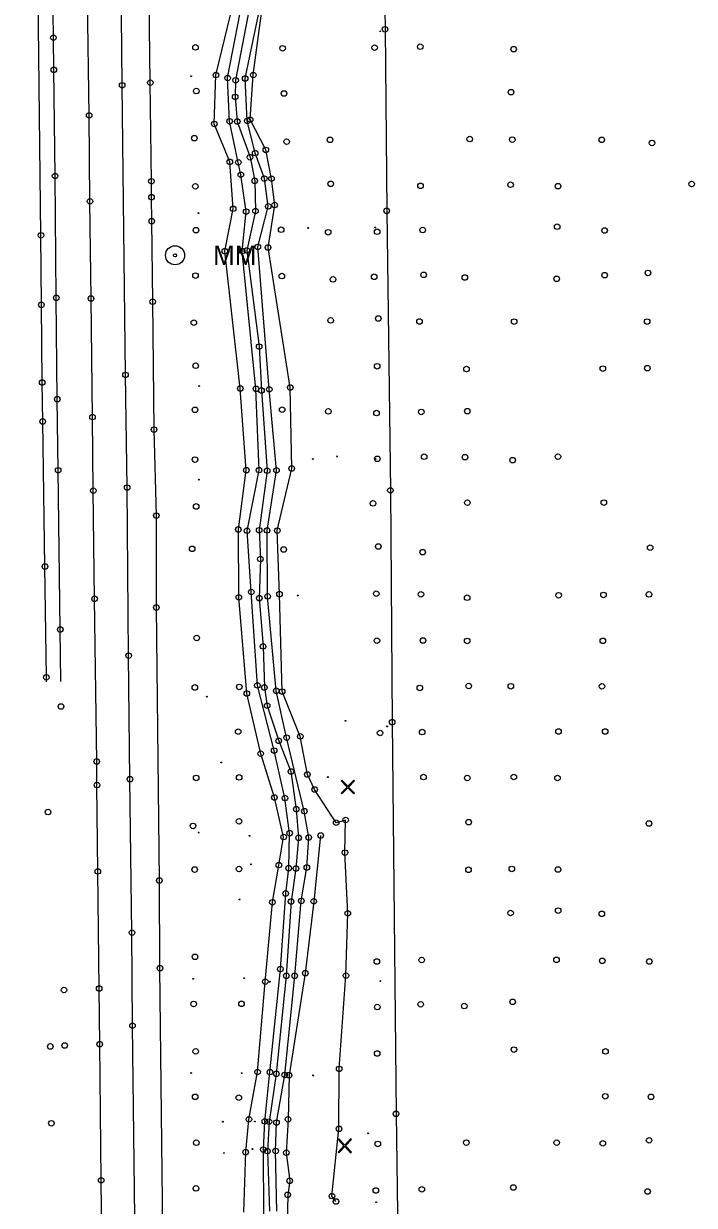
# Model space of a CAD drawing. Extents: x 20503438 to 20508873, y 7964251 to 7984667.
# Drawn here: x 20505454.4 to 20505695.9, y 7981861 to 7982286.2 of the extents above; entities that cross this region are included whole.
import ezdxf

# ---------------------------------------------------------------- set-up
doc = ezdxf.new("R2010")
doc.units = 0
for name, color, linetype in [('SurBreakLine', 7, 'Continuous'), ('SurControl', 7, 'Continuous'), ('SurDrainageArrowUp', 7, 'Continuous'), ('SurEdgeRoadPaved', 7, 'Continuous'), ('SurEdgeShoulderPaved', 7, 'Continuous'), ('SurFenceWire', 7, 'Continuous'), ('SurPointsNonDTM', 7, 'Continuous'), ('SurRoadPoints', 7, 'Continuous'), ('SurSurveyPoints', 7, 'Continuous')]:
    doc.layers.add(name, color=color, linetype=linetype)

msp = doc.modelspace()

# ---------------------------------------------------------------- linework, layer by layer
at = {"layer": 'SurBreakLine'}
for points in [[(20505533.66, 7981858.56), (20505534.37, 7981880.13), (20505535.54, 7981891.92), (20505538.65, 7981908.97), (20505541.43, 7981941.46), (20505544, 7981970.04), (20505546.31, 7981983.42), (20505548.03, 7981993.51), (20505544.72, 7982007.73), (20505539.77, 7982023.51), (20505534.8, 7982045.17), (20505531.92, 7982079.77), (20505531.73, 7982104.19), (20505534.58, 7982125.53), (20505532.44, 7982154.9), (20505526.86, 7982204.31), (20505529.86, 7982219.58), (20505528.68, 7982236.47), (20505523.06, 7982250.12), (20505523.65, 7982267.68), (20505531.03, 7982298.4)], [(20505540.86, 7981857.16), (20505540.73, 7981881.04), (20505541.27, 7981891.19), (20505543.11, 7981908.93), (20505546.87, 7981946.01), (20505548.79, 7981973.2), (20505549.87, 7981982.29), (20505550.18, 7981994.89), (20505548.49, 7982007.54), (20505544.64, 7982024.62), (20505538.6, 7982048.07), (20505536.39, 7982081.69), (20505534.88, 7982103.73), (20505539.2, 7982125.55), (20505538.07, 7982154.79), (20505533.09, 7982204.37), (20505534.53, 7982218.56), (20505532.62, 7982231.85), (20505531.72, 7982236.28), (20505528.58, 7982251.08), (20505527.86, 7982266.64), (20505534.23, 7982299.42)], [(20505482.66, 7981838.18), (20505482.35, 7981869.99), (20505481.84, 7981919), (20505481.63, 7981939.03), (20505481.16, 7981981.15), (20505480.82, 7982012.22), (20505480.73, 7982020.7), (20505479.97, 7982079.23), (20505479.51, 7982118.14), (20505479.21, 7982144.63), (20505478.7, 7982187.28), (20505478.32, 7982222.25), (20505478.02, 7982253.21), (20505477.45, 7982295.16)], [(20505545.64, 7981858.92), (20505545.16, 7981880.55), (20505545.45, 7981890.75), (20505548.44, 7981907.9), (20505552.02, 7981943.58), (20505554.39, 7981970.53), (20505556.38, 7981982.54), (20505557.08, 7981993.33), (20505555.48, 7982002.81), (20505549.12, 7982029.29), (20505545.37, 7982046.14), (20505542.28, 7982080.11), (20505542.08, 7982103.84), (20505545.47, 7982125.46), (20505542.85, 7982154.62), (20505538.74, 7982205.85), (20505542.5, 7982220.43), (20505541.11, 7982230.43), (20505537.79, 7982239.62), (20505534.95, 7982251.19), (20505534.2, 7982266.46), (20505540.46, 7982296.4)], [(20505566.86, 7981862.36), (20505565.41, 7981864.32), (20505567.96, 7981888.53), (20505568.01, 7981910.06), (20505570.48, 7981943.64), (20505571.16, 7981966.05), (20505570.1, 7981987.9), (20505570.34, 7981999.63), (20505566.96, 7981998.68), (20505559.2, 7982010.61), (20505556.59, 7982016.02), (20505554.01, 7982029.73), (20505547.49, 7982045.85), (20505546.56, 7982080.9), (20505545.76, 7982103.77), (20505550.95, 7982126.11), (20505550.41, 7982155.27), (20505542.43, 7982205.63), (20505544.81, 7982220.91), (20505543.66, 7982230.41), (20505541.61, 7982240.76), (20505535.97, 7982251.65), (20505537.1, 7982267.72), (20505540.88, 7982296.21)], [(20505561.36, 7981994.08), (20505558.88, 7981970.37), (20505555.83, 7981944.51), (20505549.98, 7981907.82), (20505549.62, 7981891.93), (20505549, 7981879.91), (20505550.23, 7981869.81), (20505549.51, 7981864.77), (20505549.3, 7981853.83), (20505549.91, 7981848.75), (20505553.2, 7981847.61)]]:
    msp.add_lwpolyline(points, dxfattribs=at)
at = {"layer": 'SurControl'}
for points in [[(20505573.56, 7982013.74), (20505573.3, 7982013.99), (20505571.16, 7982011.77), (20505569.02, 7982013.99), (20505568.76, 7982013.74), (20505570.91, 7982011.51), (20505568.76, 7982009.28), (20505569.02, 7982009.03), (20505571.16, 7982011.25), (20505573.3, 7982009.03), (20505573.56, 7982009.28), (20505571.41, 7982011.51)], [(20505572.41, 7981884.62), (20505572.15, 7981884.87), (20505570.01, 7981882.65), (20505567.87, 7981884.87), (20505567.61, 7981884.62), (20505569.76, 7981882.39), (20505567.61, 7981880.16), (20505567.87, 7981879.91), (20505570.01, 7981882.13), (20505572.15, 7981879.91), (20505572.41, 7981880.16), (20505570.26, 7981882.39)]]:
    msp.add_lwpolyline(points, close=True, dxfattribs=at)
for centre in [(20505582.84, 7982283.42), (20505514.72, 7982267.28), (20505517.35, 7982218.01), (20505556.9, 7982212.68), (20505581.02, 7982212.82), (20505517.64, 7982155.82), (20505558.52, 7982129.53), (20505567.24, 7982130.47), (20505581.09, 7982129.57), (20505517.46, 7982122.09), (20505553.1, 7982080.44), (20505520.36, 7982044.02), (20505570.32, 7982035.3), (20505585.33, 7982033.33), (20505525.55, 7982020.33), (20505563.96, 7982015.1), (20505517.45, 7981995.11), (20505535.78, 7981993.92), (20505536.18, 7981983.69), (20505532.19, 7981971.05), (20505515.45, 7981942.49), (20505533.81, 7981942.73), (20505543.03, 7981941.44), (20505582.85, 7981941.69), (20505514.74, 7981908.6), (20505532.92, 7981908.53), (20505558.7, 7981907.75), (20505526.13, 7981891.07), (20505537.66, 7981891.18), (20505578.49, 7981886.9), (20505536.86, 7981881.23), (20505526.56, 7981879.81), (20505581.34, 7981862.1)]:
    msp.add_circle(centre, 0.15, dxfattribs=at)
at = {"layer": 'SurDrainageArrowUp'}
msp.add_lwpolyline([(20505536.79, 7982297.77), (20505530.73, 7982265.81), (20505530.59, 7982259.82), (20505531.33, 7982250.97), (20505535.93, 7982238.11), (20505537.61, 7982229.63), (20505537.92, 7982218.79), (20505534.78, 7982204.62), (20505539.23, 7982169.99), (20505540.07, 7982154.17), (20505542.1, 7982125.32), (20505539.21, 7982103.89), (20505539.68, 7982093.54), (20505539.25, 7982079.46), (20505540.64, 7982062.1), (20505541.1, 7982047.32), (20505542.09, 7982040.78), (20505546.28, 7982028.14), (20505550.66, 7982017.09), (20505552.57, 7982003.52), (20505553.43, 7981993.22), (20505552.45, 7981982.2), (20505550.72, 7981970.32), (20505548.99, 7981943.58), (20505545.4, 7981908.32), (20505542.77, 7981891.09), (20505542.19, 7981880.5), (20505542.98, 7981858.88)], dxfattribs=at)
at = {"layer": 'SurEdgeRoadPaved'}
for points in [[(20505495.04, 7981807.4), (20505493.61, 7981925.64), (20505493.44, 7981959.11), (20505492.72, 7982014.35), (20505492.22, 7982058.8), (20505491.71, 7982119.25), (20505491.09, 7982159.8), (20505489.91, 7982264.01), (20505489.66, 7982289.18), (20505487.48, 7982484.19), (20505486.86, 7982538.99), (20505486.36, 7982623.82), (20505485.4, 7982711.25), (20505484.93, 7982775.73), (20505484.31, 7982835.82)], [(20505467.81, 7982049.46), (20505467.61, 7982068.18), (20505466.87, 7982125.48), (20505466.54, 7982151.08), (20505466.17, 7982187.53), (20505465.76, 7982231.38), (20505465.31, 7982269.59), (20505465.16, 7982281.14), (20505464.61, 7982327.96), (20505463.62, 7982409.11), (20505462.56, 7982525.93), (20505461.58, 7982636.16), (20505461.28, 7982673.07), (20505460.57, 7982745.92), (20505460.02, 7982819.87)]]:
    msp.add_lwpolyline(points, dxfattribs=at)
at = {"layer": 'SurEdgeShoulderPaved'}
for points in [[(20505504.9, 7981820.5), (20505503.51, 7981946.34), (20505503.3, 7981977.89), (20505502.21, 7982076.11), (20505502.21, 7982109.18), (20505501.39, 7982140.13), (20505500.91, 7982186.13), (20505500.55, 7982215.12), (20505500.48, 7982223.74), (20505500.44, 7982229.48), (20505500.04, 7982264.96), (20505498.78, 7982363.61), (20505498.7, 7982393.65), (20505498.03, 7982438.84), (20505497.19, 7982508.63), (20505496.45, 7982610.94), (20505496.22, 7982654.28), (20505495.42, 7982717.71), (20505495.4, 7982754.06), (20505495.09, 7982782.36), (20505493.62, 7982896.29)], [(20505462.63, 7982049.4), (20505462.61, 7982051), (20505462.11, 7982090.85), (20505461.3, 7982143.05), (20505461.11, 7982157.07), (20505460.83, 7982185.02), (20505460.68, 7982210.05), (20505459.25, 7982328.4), (20505458.74, 7982376.86), (20505458.32, 7982412.29), (20505458.06, 7982438.23), (20505457.12, 7982523.38), (20505456.64, 7982592.43), (20505456.16, 7982626.15), (20505455.68, 7982697.33), (20505455.16, 7982733.14), (20505454.87, 7982799.91), (20505454.43, 7982834.05)]]:
    msp.add_lwpolyline(points, dxfattribs=at)
at = {"layer": 'SurFenceWire'}
msp.add_lwpolyline([(20505583.74, 7982820.12), (20505580.19, 7982701.02), (20505581.22, 7982574.25), (20505581.59, 7982491.04), (20505582.46, 7982428.28), (20505582.73, 7982421.79), (20505583.15, 7982367.8), (20505584.54, 7982284.18), (20505585.13, 7982218.82), (20505586.48, 7982118.26), (20505587.09, 7982034.84), (20505588.49, 7981893.92), (20505589.47, 7981822.49), (20505590.29, 7981766.07)], dxfattribs=at)
at = {"layer": 'SurPointsNonDTM'}
for centre in [(20505584.54, 7982284.18), (20505585.13, 7982218.82), (20505586.48, 7982118.26), (20505587.09, 7982034.84), (20505588.49, 7981893.92)]:
    msp.add_circle(centre, 1, dxfattribs=at)
at = {"layer": 'SurRoadPoints'}
for radius in [3.43, 0.571]:
    msp.add_circle((20505508.95, 7982202.84), radius, dxfattribs=at)
at = {"layer": 'SurSurveyPoints'}
for centre in [(20505465.16, 7982281.14), (20505516.29, 7982277.65), (20505547.65, 7982277.34), (20505580.77, 7982277.54), (20505597.21, 7982277.89), (20505630.85, 7982277.03), (20505465.31, 7982269.59), (20505523.65, 7982267.68), (20505527.86, 7982266.64), (20505537.1, 7982267.72), (20505489.91, 7982264.01), (20505500.04, 7982264.96), (20505530.73, 7982265.81), (20505534.2, 7982266.46), (20505516.6, 7982261.93), (20505530.59, 7982259.82), (20505548.16, 7982261.04), (20505629.88, 7982261.54), (20505478.02, 7982253.21), (20505523.06, 7982250.12), (20505528.58, 7982251.08), (20505531.33, 7982250.97), (20505534.95, 7982251.19), (20505535.97, 7982251.65), (20505515.88, 7982244.99), (20505549.12, 7982243.73), (20505564.75, 7982244.37), (20505615.04, 7982244.66), (20505630.34, 7982244.46), (20505662.56, 7982244.37), (20505680.64, 7982243.27), (20505535.93, 7982238.11), (20505537.79, 7982239.62), (20505541.61, 7982240.76), (20505528.68, 7982236.47), (20505531.72, 7982236.28), (20505465.76, 7982231.38), (20505500.44, 7982229.48), (20505532.62, 7982231.85), (20505537.61, 7982229.63), (20505541.11, 7982230.43), (20505543.66, 7982230.41), (20505565, 7982228.57), (20505694.9, 7982228.5), (20505516.27, 7982227.65), (20505597.29, 7982227.83), (20505629.73, 7982228.22), (20505646.83, 7982227.71), (20505478.32, 7982222.25), (20505500.48, 7982223.74), (20505542.5, 7982220.43), (20505544.81, 7982220.91), (20505529.86, 7982219.58), (20505534.53, 7982218.56), (20505537.92, 7982218.79), (20505500.55, 7982215.12), (20505516.47, 7982211.87), (20505547.16, 7982212.03), (20505581.71, 7982211.31), (20505598.09, 7982211.92), (20505646.49, 7982213.12), (20505663.57, 7982211.75), (20505460.68, 7982210.05), (20505564.08, 7982211.13), (20505526.86, 7982204.31), (20505533.09, 7982204.37), (20505534.78, 7982204.62), (20505538.74, 7982205.85), (20505542.43, 7982205.63), (20505516.3, 7982195.54), (20505547.38, 7982195.37), (20505580.63, 7982195.11), (20505598.42, 7982195.82), (20505613.26, 7982194.84), (20505646.35, 7982194.38), (20505663.59, 7982195.68), (20505679.18, 7982196.5), (20505565.81, 7982194.17), (20505466.17, 7982187.53), (20505478.7, 7982187.28), (20505500.91, 7982186.13), (20505460.83, 7982185.02), (20505515.7, 7982178.59), (20505564.96, 7982179.41), (20505582.13, 7982180.08), (20505596.95, 7982179.01), (20505631.01, 7982178.97), (20505678.91, 7982178.99), (20505539.23, 7982169.99), (20505516.39, 7982163.09), (20505581.69, 7982162.92), (20505613.86, 7982161.9), (20505662.93, 7982162.06), (20505678.98, 7982162.21), (20505461.11, 7982157.07), (20505491.09, 7982159.8), (20505532.44, 7982154.9), (20505538.07, 7982154.79), (20505540.07, 7982154.17), (20505542.85, 7982154.62), (20505550.41, 7982155.27), (20505466.54, 7982151.08), (20505479.21, 7982144.63), (20505516.11, 7982147.23), (20505547.52, 7982147.29), (20505564.14, 7982146.67), (20505581.47, 7982146.06), (20505597.57, 7982146.47), (20505614.17, 7982146.76), (20505461.3, 7982143.05), (20505501.39, 7982140.13), (20505516.12, 7982129.33), (20505581.75, 7982129.59), (20505598.62, 7982130.36), (20505613.35, 7982130.19), (20505630.47, 7982129.13), (20505646.79, 7982130.38), (20505466.87, 7982125.48), (20505534.58, 7982125.53), (20505539.2, 7982125.55), (20505542.1, 7982125.32), (20505545.47, 7982125.46), (20505550.95, 7982126.11), (20505479.51, 7982118.14), (20505491.71, 7982119.25), (20505580.18, 7982113.57), (20505614.17, 7982113.83), (20505663.31, 7982113.85), (20505516.56, 7982112.47), (20505502.21, 7982109.18), (20505531.73, 7982104.19), (20505534.88, 7982103.73), (20505539.21, 7982103.89), (20505542.08, 7982103.84), (20505545.76, 7982103.77), (20505515.1, 7982097.21), (20505548.06, 7982096.98), (20505582.11, 7982098.06), (20505680, 7982097.63), (20505539.68, 7982093.54), (20505598.09, 7982096.03), (20505462.11, 7982090.85), (20505531.92, 7982079.77), (20505536.39, 7982081.69), (20505539.25, 7982079.46), (20505542.28, 7982080.11), (20505546.56, 7982080.9), (20505581.37, 7982081.09), (20505597.45, 7982080.85), (20505614.12, 7982079.62), (20505647.04, 7982080.51), (20505663.18, 7982080.62), (20505679.54, 7982080.82), (20505479.97, 7982079.23), (20505502.21, 7982076.11), (20505467.61, 7982068.18), (20505516.75, 7982065.13), (20505581.61, 7982064.18), (20505598.21, 7982064.22), (20505614.09, 7982064.07), (20505662.95, 7982064.11), (20505492.22, 7982058.8), (20505540.64, 7982062.1), (20505462.61, 7982051), (20505516.08, 7982047.34), (20505532.05, 7982047.53), (20505538.6, 7982048.07), (20505541.1, 7982047.32), (20505545.37, 7982046.14), (20505547.49, 7982045.85), (20505597.08, 7982047.17), (20505614.67, 7982047.87), (20505629.82, 7982047.77), (20505662.62, 7982047.75), (20505534.8, 7982045.17), (20505467.91, 7982040.47), (20505542.09, 7982040.78), (20505531.65, 7982031.42), (20505549.12, 7982029.29), (20505554.01, 7982029.73), (20505582.76, 7982030.95), (20505597.92, 7982031.27), (20505647, 7982031.5), (20505663.77, 7982031.48), (20505544.64, 7982024.62), (20505546.28, 7982028.14), (20505480.73, 7982020.7), (20505539.77, 7982023.51), (20505550.66, 7982017.09), (20505556.59, 7982016.02), (20505480.82, 7982012.22), (20505492.72, 7982014.35), (20505516.54, 7982014.79), (20505532.01, 7982014.96), (20505598.38, 7982015.1), (20505614.15, 7982014.75), (20505630.92, 7982015.12), (20505646.63, 7982014.75), (20505544.72, 7982007.73), (20505548.49, 7982007.54), (20505559.2, 7982010.61), (20505552.57, 7982003.52), (20505463.22, 7982002.49), (20505531.99, 7981999.17), (20505555.48, 7982002.81), (20505566.96, 7981998.68), (20505570.34, 7981999.63), (20505614.62, 7981998.86), (20505515.42, 7981997.51), (20505550.18, 7981994.89), (20505679.55, 7981998.4), (20505548.03, 7981993.51), (20505553.43, 7981993.22), (20505557.08, 7981993.33), (20505561.36, 7981994.08), (20505570.1, 7981987.9), (20505516, 7981981.81), (20505531.98, 7981982.02), (20505546.31, 7981983.42), (20505549.87, 7981982.29), (20505552.45, 7981982.2), (20505556.38, 7981982.54), (20505614.58, 7981981.73), (20505630.17, 7981982.04), (20505646.82, 7981981.84), (20505481.16, 7981981.15), (20505503.3, 7981977.89), (20505548.79, 7981973.2), (20505544, 7981970.04), (20505550.72, 7981970.32), (20505554.39, 7981970.53), (20505558.88, 7981970.37), (20505571.16, 7981966.05), (20505629.73, 7981966.18), (20505646.87, 7981967.03), (20505662.59, 7981965.89), (20505493.44, 7981959.11), (20505516.14, 7981950.4), (20505581.6, 7981948.74), (20505597.72, 7981949.27), (20505646.26, 7981949.31), (20505662.73, 7981948.96), (20505679.69, 7981948.73), (20505503.51, 7981946.34), (20505546.87, 7981946.01), (20505548.99, 7981943.58), (20505552.02, 7981943.58), (20505555.83, 7981944.51), (20505570.48, 7981943.64), (20505541.43, 7981941.46), (20505468.96, 7981938.47), (20505481.63, 7981939.03), (20505515.64, 7981933.45), (20505532.86, 7981933.5), (20505581.76, 7981932.33), (20505597.37, 7981933.31), (20505613.05, 7981932.69), (20505630.49, 7981934.22), (20505493.61, 7981925.64), (20505464.05, 7981918.16), (20505469.2, 7981918.48), (20505481.84, 7981919), (20505516.37, 7981916.41), (20505581.69, 7981915.62), (20505630.93, 7981917.03), (20505663.92, 7981916.37), (20505568.01, 7981910.06), (20505538.65, 7981908.97), (20505543.11, 7981908.93), (20505545.4, 7981908.32), (20505548.44, 7981907.9), (20505549.98, 7981907.82), (20505516.18, 7981900.04), (20505531.92, 7981899.74), (20505663.81, 7981900.24), (20505680.29, 7981900.03), (20505464.43, 7981890.53), (20505535.54, 7981891.92), (20505541.27, 7981891.19), (20505542.77, 7981891.09), (20505545.45, 7981890.75), (20505549.62, 7981891.93), (20505567.96, 7981888.53), (20505679.6, 7981884.37), (20505516.58, 7981883.51), (20505534.37, 7981880.13), (20505540.73, 7981881.04), (20505542.19, 7981880.5), (20505545.16, 7981880.55), (20505549, 7981879.91), (20505581.95, 7981883.08), (20505613.81, 7981883.55), (20505646.34, 7981883.54), (20505662.94, 7981883.3), (20505482.35, 7981869.99), (20505516.46, 7981867.09), (20505550.23, 7981869.81), (20505630.75, 7981867.41), (20505549.51, 7981864.77), (20505565.41, 7981864.32), (20505581.24, 7981866.33), (20505597.79, 7981866.75), (20505679.05, 7981865.98), (20505566.86, 7981862.36)]:
    msp.add_circle(centre, 1, dxfattribs=at)

# ---------------------------------------------------------------- texts
at = {"layer": 'SurRoadPoints'}
msp.add_text('MM', height=6.995, rotation=360, dxfattribs=at).set_placement((20505522.66, 7982199.35))

doc.saveas('drawing.dxf')
